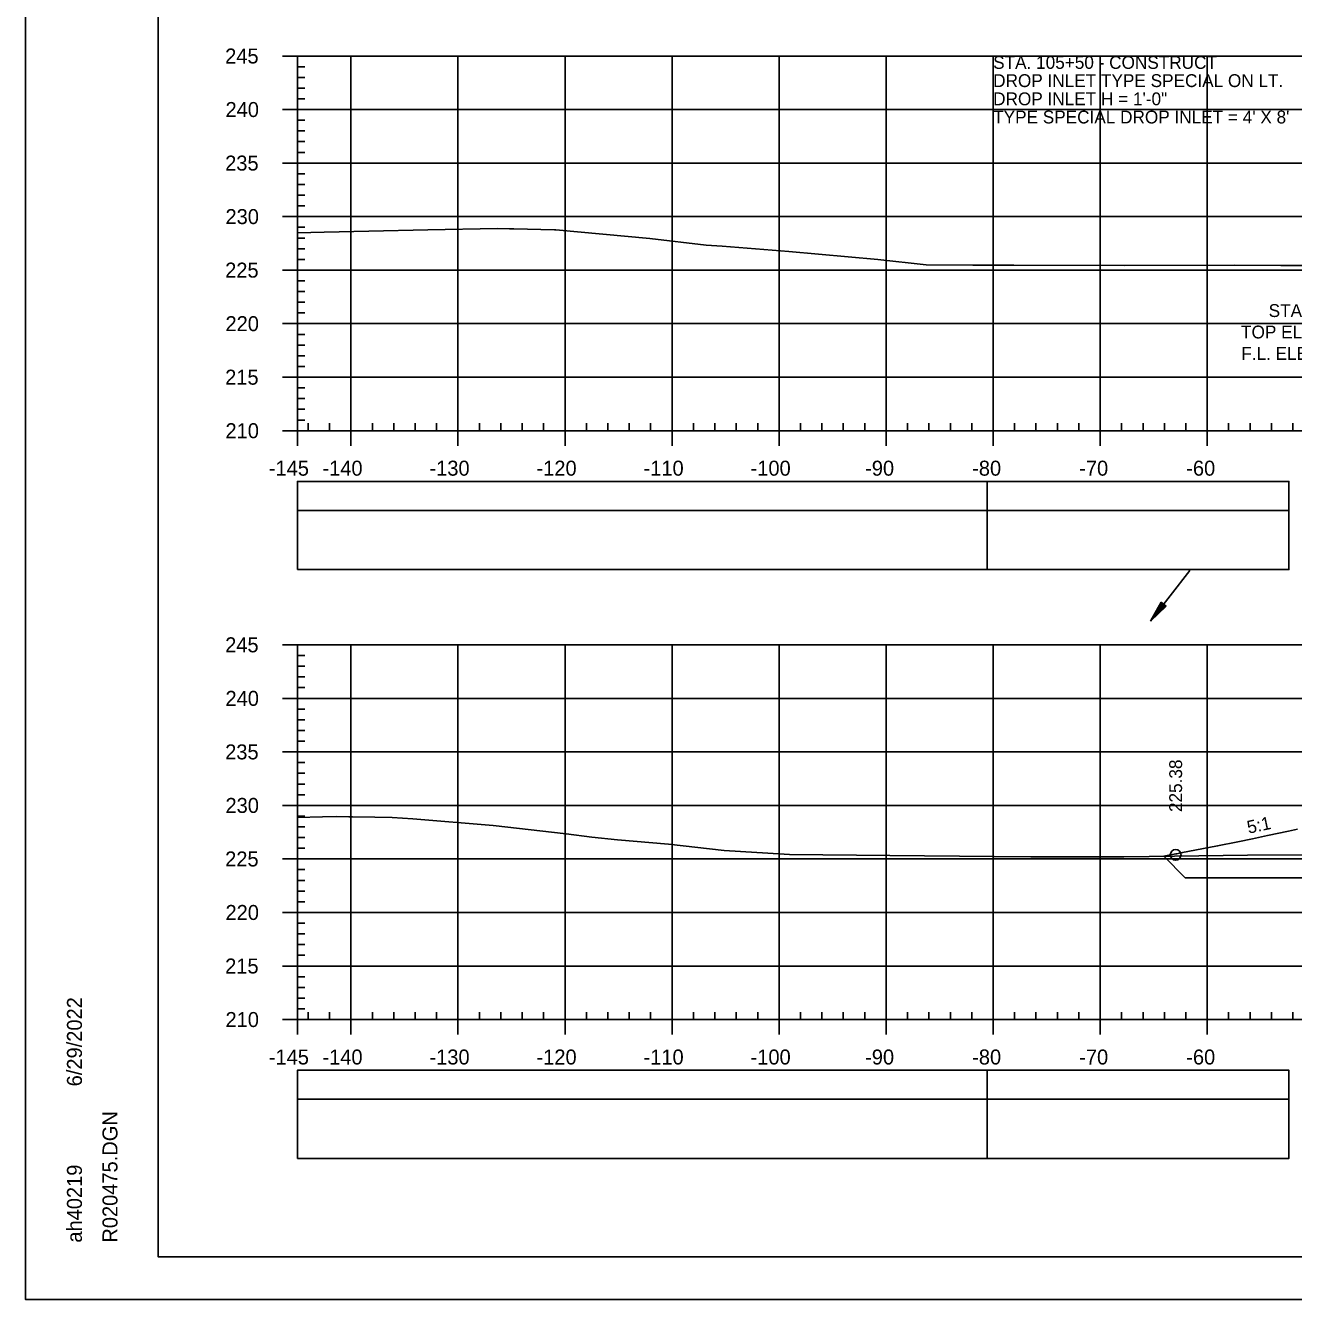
# Model space of a CAD drawing. Extents: x 1386544 to 1388153, y 379785 to 390999.
# Drawn here: x 1387761.6 to 1387880, y 380518.8 to 380637.8 of the extents above; entities that cross this region are included whole.
import ezdxf

# ---------------------------------------------------------------- set-up
doc = ezdxf.new("R2010")
doc.units = 0
for name, color, linetype in [('R_Axis', 7, 'Continuous'), ('R_Axis Annot', 7, 'Continuous'), ('R_Border', 7, 'Continuous'), ('R_Dimension', 7, 'Continuous'), ('R_Exist Surface', 7, 'Continuous'), ('R_Fin Surface', 7, 'Continuous'), ('R_Fin Surface Annot', 7, 'Continuous'), ('R_Grid', 7, 'Continuous'), ('R_No Plot', 7, 'Continuous'), ('R_Striping', 7, 'Continuous'), ('R_Water', 7, 'Continuous'), ('R_Water Annot', 7, 'Continuous')]:
    doc.layers.add(name, color=color, linetype=linetype)

msp = doc.modelspace()

# ---------------------------------------------------------------- linework, layer by layer
at = {"layer": 'R_Axis'}
for p, q in [((1387785.57, 380634.95), (1387786.97, 380634.95)), ((1387786.97, 380599.95), (1387786.97, 380634.95)), ((1387786.97, 380633.95), (1387787.67, 380633.95)), ((1387786.97, 380632.95), (1387787.67, 380632.95)), ((1387786.97, 380631.95), (1387787.67, 380631.95)), ((1387785.57, 380629.95), (1387786.97, 380629.95)), ((1387786.97, 380630.95), (1387787.67, 380630.95)), ((1387786.97, 380628.95), (1387787.67, 380628.95)), ((1387786.97, 380627.95), (1387787.67, 380627.95)), ((1387786.97, 380626.95), (1387787.67, 380626.95)), ((1387786.97, 380625.95), (1387787.67, 380625.95)), ((1387785.57, 380624.95), (1387786.97, 380624.95)), ((1387786.97, 380623.95), (1387787.67, 380623.95)), ((1387786.97, 380622.95), (1387787.67, 380622.95)), ((1387786.97, 380621.95), (1387787.67, 380621.95)), ((1387786.97, 380620.95), (1387787.67, 380620.95)), ((1387785.57, 380619.95), (1387786.97, 380619.95)), ((1387786.97, 380618.95), (1387787.67, 380618.95)), ((1387786.97, 380617.95), (1387787.67, 380617.95)), ((1387786.97, 380616.95), (1387787.67, 380616.95)), ((1387786.97, 380615.95), (1387787.67, 380615.95)), ((1387785.57, 380614.95), (1387786.97, 380614.95)), ((1387786.97, 380613.95), (1387787.67, 380613.95)), ((1387786.97, 380612.95), (1387787.67, 380612.95)), ((1387786.97, 380611.95), (1387787.67, 380611.95)), ((1387786.97, 380610.95), (1387787.67, 380610.95)), ((1387785.57, 380609.95), (1387786.97, 380609.95)), ((1387786.97, 380608.95), (1387787.67, 380608.95)), ((1387786.97, 380607.95), (1387787.67, 380607.95)), ((1387786.97, 380606.95), (1387787.67, 380606.95)), ((1387785.57, 380604.95), (1387786.97, 380604.95)), ((1387786.97, 380605.95), (1387787.67, 380605.95)), ((1387786.97, 380603.95), (1387787.67, 380603.95)), ((1387786.97, 380602.95), (1387787.67, 380602.95)), ((1387786.97, 380601.95), (1387787.67, 380601.95)), ((1387786.97, 380600.95), (1387787.67, 380600.95)), ((1387786.97, 380599.95), (1387786.97, 380600.65)), ((1387787.97, 380599.95), (1387787.97, 380600.65)), ((1387789.97, 380599.95), (1387789.97, 380600.65)), ((1387793.97, 380599.95), (1387793.97, 380600.65)), ((1387795.97, 380599.95), (1387795.97, 380600.65)), ((1387797.97, 380599.95), (1387797.97, 380600.65)), ((1387799.97, 380599.95), (1387799.97, 380600.65)), ((1387803.97, 380599.95), (1387803.97, 380600.65)), ((1387805.97, 380599.95), (1387805.97, 380600.65)), ((1387807.97, 380599.95), (1387807.97, 380600.65)), ((1387809.97, 380599.95), (1387809.97, 380600.65)), ((1387813.97, 380599.95), (1387813.97, 380600.65)), ((1387815.97, 380599.95), (1387815.97, 380600.65)), ((1387817.97, 380599.95), (1387817.97, 380600.65)), ((1387819.97, 380599.95), (1387819.97, 380600.65)), ((1387823.97, 380599.95), (1387823.97, 380600.65)), ((1387825.97, 380599.95), (1387825.97, 380600.65)), ((1387827.97, 380599.95), (1387827.97, 380600.65)), ((1387829.97, 380599.95), (1387829.97, 380600.65)), ((1387833.97, 380599.95), (1387833.97, 380600.65)), ((1387835.97, 380599.95), (1387835.97, 380600.65)), ((1387837.97, 380599.95), (1387837.97, 380600.65)), ((1387839.97, 380599.95), (1387839.97, 380600.65)), ((1387843.97, 380599.95), (1387843.97, 380600.65)), ((1387845.97, 380599.95), (1387845.97, 380600.65)), ((1387847.97, 380599.95), (1387847.97, 380600.65)), ((1387849.97, 380599.95), (1387849.97, 380600.65)), ((1387853.97, 380599.95), (1387853.97, 380600.65)), ((1387855.97, 380599.95), (1387855.97, 380600.65)), ((1387857.97, 380599.95), (1387857.97, 380600.65)), ((1387859.97, 380599.95), (1387859.97, 380600.65)), ((1387863.97, 380599.95), (1387863.97, 380600.65)), ((1387865.97, 380599.95), (1387865.97, 380600.65)), ((1387867.97, 380599.95), (1387867.97, 380600.65)), ((1387869.97, 380599.95), (1387869.97, 380600.65)), ((1387873.97, 380599.95), (1387873.97, 380600.65)), ((1387875.97, 380599.95), (1387875.97, 380600.65)), ((1387877.97, 380599.95), (1387877.97, 380600.65)), ((1387879.97, 380599.95), (1387879.97, 380600.65)), ((1387785.57, 380599.95), (1387786.97, 380599.95)), ((1387786.97, 380599.95), (1388076.97, 380599.95)), ((1387786.97, 380598.55), (1387786.97, 380599.95)), ((1387791.97, 380598.55), (1387791.97, 380599.95)), ((1387801.97, 380598.55), (1387801.97, 380599.95)), ((1387811.97, 380598.55), (1387811.97, 380599.95)), ((1387821.97, 380598.55), (1387821.97, 380599.95)), ((1387831.97, 380598.55), (1387831.97, 380599.95)), ((1387841.97, 380598.55), (1387841.97, 380599.95)), ((1387851.97, 380598.55), (1387851.97, 380599.95)), ((1387861.97, 380598.55), (1387861.97, 380599.95)), ((1387871.97, 380598.55), (1387871.97, 380599.95)), ((1387785.57, 380579.95), (1387786.97, 380579.95)), ((1387786.97, 380544.95), (1387786.97, 380579.95)), ((1387786.97, 380578.95), (1387787.67, 380578.95)), ((1387786.97, 380577.95), (1387787.67, 380577.95)), ((1387786.97, 380576.95), (1387787.67, 380576.95)), ((1387786.97, 380575.95), (1387787.67, 380575.95)), ((1387785.57, 380574.95), (1387786.97, 380574.95)), ((1387786.97, 380573.95), (1387787.67, 380573.95)), ((1387786.97, 380572.95), (1387787.67, 380572.95)), ((1387786.97, 380571.95), (1387787.67, 380571.95)), ((1387786.97, 380570.95), (1387787.67, 380570.95)), ((1387785.57, 380569.95), (1387786.97, 380569.95)), ((1387786.97, 380568.95), (1387787.67, 380568.95)), ((1387786.97, 380567.95), (1387787.67, 380567.95)), ((1387786.97, 380566.95), (1387787.67, 380566.95)), ((1387786.97, 380565.95), (1387787.67, 380565.95)), ((1387785.57, 380564.95), (1387786.97, 380564.95)), ((1387786.97, 380563.95), (1387787.67, 380563.95)), ((1387786.97, 380562.95), (1387787.67, 380562.95)), ((1387786.97, 380561.95), (1387787.67, 380561.95)), ((1387786.97, 380560.95), (1387787.67, 380560.95)), ((1387785.57, 380559.95), (1387786.97, 380559.95)), ((1387786.97, 380558.95), (1387787.67, 380558.95)), ((1387786.97, 380557.95), (1387787.67, 380557.95)), ((1387786.97, 380556.95), (1387787.67, 380556.95)), ((1387785.57, 380554.95), (1387786.97, 380554.95)), ((1387786.97, 380555.95), (1387787.67, 380555.95)), ((1387786.97, 380553.95), (1387787.67, 380553.95)), ((1387786.97, 380552.95), (1387787.67, 380552.95)), ((1387786.97, 380551.95), (1387787.67, 380551.95)), ((1387786.97, 380550.95), (1387787.67, 380550.95)), ((1387785.57, 380549.95), (1387786.97, 380549.95)), ((1387786.97, 380548.95), (1387787.67, 380548.95)), ((1387786.97, 380547.95), (1387787.67, 380547.95)), ((1387786.97, 380546.95), (1387787.67, 380546.95)), ((1387786.97, 380545.95), (1387787.67, 380545.95)), ((1387786.97, 380544.95), (1387786.97, 380545.65)), ((1387787.97, 380544.95), (1387787.97, 380545.65)), ((1387789.97, 380544.95), (1387789.97, 380545.65)), ((1387793.97, 380544.95), (1387793.97, 380545.65)), ((1387795.97, 380544.95), (1387795.97, 380545.65)), ((1387797.97, 380544.95), (1387797.97, 380545.65)), ((1387799.97, 380544.95), (1387799.97, 380545.65)), ((1387803.97, 380544.95), (1387803.97, 380545.65)), ((1387805.97, 380544.95), (1387805.97, 380545.65)), ((1387807.97, 380544.95), (1387807.97, 380545.65)), ((1387809.97, 380544.95), (1387809.97, 380545.65)), ((1387813.97, 380544.95), (1387813.97, 380545.65)), ((1387815.97, 380544.95), (1387815.97, 380545.65)), ((1387817.97, 380544.95), (1387817.97, 380545.65)), ((1387819.97, 380544.95), (1387819.97, 380545.65)), ((1387823.97, 380544.95), (1387823.97, 380545.65)), ((1387825.97, 380544.95), (1387825.97, 380545.65)), ((1387827.97, 380544.95), (1387827.97, 380545.65)), ((1387829.97, 380544.95), (1387829.97, 380545.65)), ((1387833.97, 380544.95), (1387833.97, 380545.65)), ((1387835.97, 380544.95), (1387835.97, 380545.65)), ((1387837.97, 380544.95), (1387837.97, 380545.65)), ((1387839.97, 380544.95), (1387839.97, 380545.65)), ((1387843.97, 380544.95), (1387843.97, 380545.65)), ((1387845.97, 380544.95), (1387845.97, 380545.65)), ((1387847.97, 380544.95), (1387847.97, 380545.65)), ((1387849.97, 380544.95), (1387849.97, 380545.65)), ((1387853.97, 380544.95), (1387853.97, 380545.65)), ((1387855.97, 380544.95), (1387855.97, 380545.65)), ((1387857.97, 380544.95), (1387857.97, 380545.65)), ((1387859.97, 380544.95), (1387859.97, 380545.65)), ((1387863.97, 380544.95), (1387863.97, 380545.65)), ((1387865.97, 380544.95), (1387865.97, 380545.65)), ((1387867.97, 380544.95), (1387867.97, 380545.65)), ((1387869.97, 380544.95), (1387869.97, 380545.65)), ((1387873.97, 380544.95), (1387873.97, 380545.65)), ((1387875.97, 380544.95), (1387875.97, 380545.65)), ((1387877.97, 380544.95), (1387877.97, 380545.65)), ((1387879.97, 380544.95), (1387879.97, 380545.65)), ((1387785.57, 380544.95), (1387786.97, 380544.95)), ((1387786.97, 380544.95), (1388076.97, 380544.95)), ((1387786.97, 380543.55), (1387786.97, 380544.95)), ((1387791.97, 380543.55), (1387791.97, 380544.95)), ((1387801.97, 380543.55), (1387801.97, 380544.95)), ((1387811.97, 380543.55), (1387811.97, 380544.95)), ((1387821.97, 380543.55), (1387821.97, 380544.95)), ((1387831.97, 380543.55), (1387831.97, 380544.95)), ((1387841.97, 380543.55), (1387841.97, 380544.95)), ((1387851.97, 380543.55), (1387851.97, 380544.95)), ((1387861.97, 380543.55), (1387861.97, 380544.95)), ((1387871.97, 380543.55), (1387871.97, 380544.95))]:
    msp.add_line(p, q, dxfattribs=at)
at = {"layer": 'R_Axis Annot'}
for points in [[(1387786.97, 380592.5), (1387851.41, 380592.5), (1387851.41, 380595.21), (1387786.97, 380595.21)], [(1387786.97, 380586.98), (1387851.41, 380586.98), (1387851.41, 380592.5), (1387786.97, 380592.5)], [(1387786.97, 380537.5), (1387851.41, 380537.5), (1387851.41, 380540.21), (1387786.97, 380540.21)], [(1387786.97, 380531.98), (1387851.41, 380531.98), (1387851.41, 380537.5), (1387786.97, 380537.5)]]:
    msp.add_lwpolyline(points, close=True, dxfattribs=at)
at = {"layer": 'R_Border'}
for p, q in [((1387773.97, 380522.78), (1387773.97, 380728.24)), ((1387773.97, 380522.78), (1387773.97, 380522.78)), ((1388090.15, 380522.78), (1387773.97, 380522.78))]:
    msp.add_line(p, q, dxfattribs=at)
at = {"layer": 'R_Dimension'}
msp.add_line((1387867.91, 380560.2), (1387869.91, 380558.2), dxfattribs=at)
msp.add_lwpolyline([(1387869.91, 380558.2), (1387908.95, 380558.2)], dxfattribs=at)
at = {"layer": 'R_Exist Surface'}
for points in [[(1387786.97, 380618.42), (1387789.46, 380618.49), (1387793.65, 380618.59), (1387799.17, 380618.72), (1387805.66, 380618.85), (1387806.78, 380618.8), (1387807.19, 380618.8), (1387810.98, 380618.72), (1387811.01, 380618.72), (1387811.1, 380618.72), (1387819.88, 380617.89), (1387825.15, 380617.29), (1387826.65, 380617.2), (1387832.87, 380616.69), (1387841.2, 380615.94), (1387845.71, 380615.45), (1387850.08, 380615.4), (1387853.89, 380615.41), (1387864.26, 380615.39), (1387874.52, 380615.41), (1387878.85, 380615.37), (1387879.83, 380615.37), (1387882.47, 380615.37)], [(1387786.97, 380563.82), (1387789.3, 380563.89), (1387790.66, 380563.92), (1387791.76, 380563.89), (1387792.13, 380563.88), (1387794.19, 380563.85), (1387795.83, 380563.82), (1387797.76, 380563.69), (1387805.25, 380563.08), (1387812.08, 380562.3), (1387814.47, 380561.99), (1387816.89, 380561.74), (1387821.65, 380561.32), (1387826.83, 380560.73), (1387832.45, 380560.39), (1387832.95, 380560.38), (1387842.31, 380560.28), (1387852.08, 380560.19), (1387855.48, 380560.15), (1387864.18, 380560.16), (1387868.9, 380560.22), (1387875.73, 380560.3), (1387896.5, 380560.38)]]:
    msp.add_lwpolyline(points, dxfattribs=at)
at = {"layer": 'R_Fin Surface'}
for points in [[(1387869.14, 380560.44), (1387869.67, 380560.54), (1387872.11, 380561.01), (1387872.93, 380561.17), (1387874.84, 380561.56), (1387876.21, 380561.83), (1387877.6, 380562.13), (1387879.55, 380562.54), (1387880.4, 380562.73)], [(1387867.91, 380560.2), (1387869.05, 380560.42), (1387869.14, 380560.44), (1387869.14, 380560.44)]]:
    msp.add_lwpolyline(points, dxfattribs=at)
at = {"layer": 'R_Grid'}
for p, q in [((1387786.97, 380634.95), (1388076.97, 380634.95)), ((1387786.97, 380599.95), (1387786.97, 380634.95)), ((1387791.97, 380599.95), (1387791.97, 380634.95)), ((1387801.97, 380599.95), (1387801.97, 380634.95)), ((1387811.97, 380599.95), (1387811.97, 380634.95)), ((1387821.97, 380599.95), (1387821.97, 380634.95)), ((1387831.97, 380599.95), (1387831.97, 380634.95)), ((1387841.97, 380599.95), (1387841.97, 380634.95)), ((1387851.97, 380599.95), (1387851.97, 380634.95)), ((1387861.97, 380599.95), (1387861.97, 380634.95)), ((1387871.97, 380599.95), (1387871.97, 380634.95)), ((1387786.97, 380629.95), (1388076.97, 380629.95)), ((1387786.97, 380624.95), (1388076.97, 380624.95)), ((1387786.97, 380619.95), (1388076.97, 380619.95)), ((1387786.97, 380614.95), (1388076.97, 380614.95)), ((1387786.97, 380609.95), (1388076.97, 380609.95)), ((1387786.97, 380604.95), (1388076.97, 380604.95)), ((1387786.97, 380599.95), (1388076.97, 380599.95)), ((1387786.97, 380579.95), (1388076.97, 380579.95)), ((1387786.97, 380544.95), (1387786.97, 380579.95)), ((1387791.97, 380544.95), (1387791.97, 380579.95)), ((1387801.97, 380544.95), (1387801.97, 380579.95)), ((1387811.97, 380544.95), (1387811.97, 380579.95)), ((1387821.97, 380544.95), (1387821.97, 380579.95)), ((1387831.97, 380544.95), (1387831.97, 380579.95)), ((1387841.97, 380544.95), (1387841.97, 380579.95)), ((1387851.97, 380544.95), (1387851.97, 380579.95)), ((1387861.97, 380544.95), (1387861.97, 380579.95)), ((1387871.97, 380544.95), (1387871.97, 380579.95)), ((1387786.97, 380574.95), (1388076.97, 380574.95)), ((1387786.97, 380569.95), (1388076.97, 380569.95)), ((1387786.97, 380564.95), (1388076.97, 380564.95)), ((1387786.97, 380559.95), (1388076.97, 380559.95)), ((1387786.97, 380554.95), (1388076.97, 380554.95)), ((1387786.97, 380549.95), (1388076.97, 380549.95)), ((1387786.97, 380544.95), (1388076.97, 380544.95))]:
    msp.add_line(p, q, dxfattribs=at)
at = {"layer": 'R_No Plot'}
msp.add_line((1387761.57, 380518.8), (1388094.9, 380518.8), dxfattribs=at)
for points in [[(1387761.56, 380732.14), (1388094.9, 380732.14), (1388094.9, 380518.8), (1387761.56, 380518.8)], [(1388007.89, 380728.24), (1388027.51, 380728.24), (1388027.51, 380718.36), (1388043.62, 380718.36), (1388066.82, 380718.36), (1388066.82, 380694.03), (1388090.15, 380694.03), (1388090.15, 380522.78), (1387773.97, 380522.78), (1387773.97, 380728.24)]]:
    msp.add_lwpolyline(points, close=True, dxfattribs=at)
msp.add_circle((1387869.02, 380560.33), 0.5, dxfattribs=at)
at = {"layer": 'R_Striping'}
for points in [[(1387851.41, 380592.51), (1387879.6, 380592.51), (1387879.6, 380595.21), (1387851.41, 380595.21)], [(1387851.41, 380586.98), (1387879.6, 380586.98), (1387879.6, 380592.51), (1387851.41, 380592.51)], [(1387851.41, 380537.51), (1387879.6, 380537.51), (1387879.6, 380540.21), (1387851.41, 380540.21)], [(1387851.41, 380531.98), (1387879.6, 380531.98), (1387879.6, 380537.51), (1387851.41, 380537.51)]]:
    msp.add_lwpolyline(points, close=True, dxfattribs=at)
at = {"layer": 'R_Water'}
for p, q in [((1387870.35, 380586.9), (1387866.67, 380582.16)), ((1387867.66, 380583.93), (1387866.67, 380582.16)), ((1387867.66, 380583.93), (1387866.67, 380582.16)), ((1387868.13, 380583.56), (1387866.67, 380582.16)), ((1387868.13, 380583.56), (1387866.67, 380582.16)), ((1387867.7, 380583.9), (1387866.87, 380582.43)), ((1387867.7, 380583.9), (1387866.87, 380582.43)), ((1387868.09, 380583.59), (1387866.87, 380582.43)), ((1387868.09, 380583.59), (1387866.87, 380582.43)), ((1387867.74, 380583.87), (1387867.08, 380582.7)), ((1387867.74, 380583.87), (1387867.08, 380582.7)), ((1387868.05, 380583.62), (1387867.08, 380582.7)), ((1387868.05, 380583.62), (1387867.08, 380582.7)), ((1387867.78, 380583.84), (1387867.29, 380582.96)), ((1387867.78, 380583.84), (1387867.29, 380582.96)), ((1387868.01, 380583.65), (1387867.29, 380582.96)), ((1387868.01, 380583.65), (1387867.29, 380582.96)), ((1387867.82, 380583.8), (1387867.5, 380583.23)), ((1387867.82, 380583.8), (1387867.5, 380583.23)), ((1387867.97, 380583.68), (1387867.5, 380583.23)), ((1387867.97, 380583.68), (1387867.5, 380583.23)), ((1387868.13, 380583.56), (1387867.66, 380583.93)), ((1387868.13, 380583.56), (1387867.66, 380583.93)), ((1387867.86, 380583.77), (1387867.7, 380583.49)), ((1387867.86, 380583.77), (1387867.7, 380583.49)), ((1387867.93, 380583.72), (1387867.7, 380583.49)), ((1387867.93, 380583.72), (1387867.7, 380583.49))]:
    msp.add_line(p, q, dxfattribs=at)

# ---------------------------------------------------------------- texts
at = {"layer": 'R_Axis Annot'}
for s, p in [('245', (1387780.22, 380634.25)), ('240', (1387780.25, 380629.25)), ('235', (1387780.22, 380624.25)), ('230', (1387780.25, 380619.25)), ('225', (1387780.22, 380614.25)), ('220', (1387780.25, 380609.25)), ('215', (1387780.22, 380604.25)), ('210', (1387780.25, 380599.25)), ('-145', (1387784.3, 380595.75)), ('-140', (1387789.31, 380595.75)), ('-130', (1387799.31, 380595.75)), ('-120', (1387809.31, 380595.75)), ('-110', (1387819.31, 380595.75)), ('-100', (1387829.31, 380595.75)), ('-90', (1387840.01, 380595.75)), ('-80', (1387850.01, 380595.75)), ('-70', (1387860.01, 380595.75)), ('-60', (1387870.01, 380595.75)), ('245', (1387780.22, 380579.25)), ('240', (1387780.25, 380574.25)), ('235', (1387780.22, 380569.25)), ('230', (1387780.25, 380564.25)), ('225', (1387780.22, 380559.25)), ('220', (1387780.25, 380554.25)), ('215', (1387780.22, 380549.25)), ('210', (1387780.25, 380544.25)), ('-145', (1387784.3, 380540.75)), ('-140', (1387789.31, 380540.75)), ('-130', (1387799.31, 380540.75)), ('-120', (1387809.31, 380540.75)), ('-110', (1387819.31, 380540.75)), ('-100', (1387829.31, 380540.75)), ('-90', (1387840.01, 380540.75)), ('-80', (1387850.01, 380540.75)), ('-70', (1387860.01, 380540.75)), ('-60', (1387870.01, 380540.75))]:
    msp.add_text(s, height=1.4, dxfattribs=at).set_placement(p)
at = {"layer": 'R_Border'}
for s, p in [('6/29/2022', (1387766.84, 380538.71)), ('R020475.DGN', (1387770.16, 380524.11)), ('ah40219', (1387766.84, 380524.11))]:
    msp.add_text(s, height=1.4, rotation=90, dxfattribs=at).set_placement(p)
at = {"layer": 'R_Fin Surface Annot'}
for s, rotation, p in [('225.38', 90, (1387869.62, 380564.33)), ('5:1', 12.0984, (1387875.83, 380562.3))]:
    msp.add_text(s, height=1.2, rotation=rotation, dxfattribs=at).set_placement(p)
at = {"layer": 'R_Water Annot'}
for s, p in [('STA. 105+50 - CONSTRUCT', (1387851.97, 380633.75)), ('DROP INLET TYPE SPECIAL ON LT.', (1387851.97, 380632.05)), ('DROP INLET H = 1\'-0"', (1387851.97, 380630.35)), ("TYPE SPECIAL DROP INLET = 4' X 8'", (1387851.97, 380628.65)), ('STA. 105+50', (1387877.71, 380610.57)), ('TOP ELEV.=228.19', (1387875.13, 380608.57)), ('F.L. ELEV.=225.42', (1387875.15, 380606.57))]:
    msp.add_text(s, height=1.2, dxfattribs=at).set_placement(p)

doc.saveas('drawing.dxf')
